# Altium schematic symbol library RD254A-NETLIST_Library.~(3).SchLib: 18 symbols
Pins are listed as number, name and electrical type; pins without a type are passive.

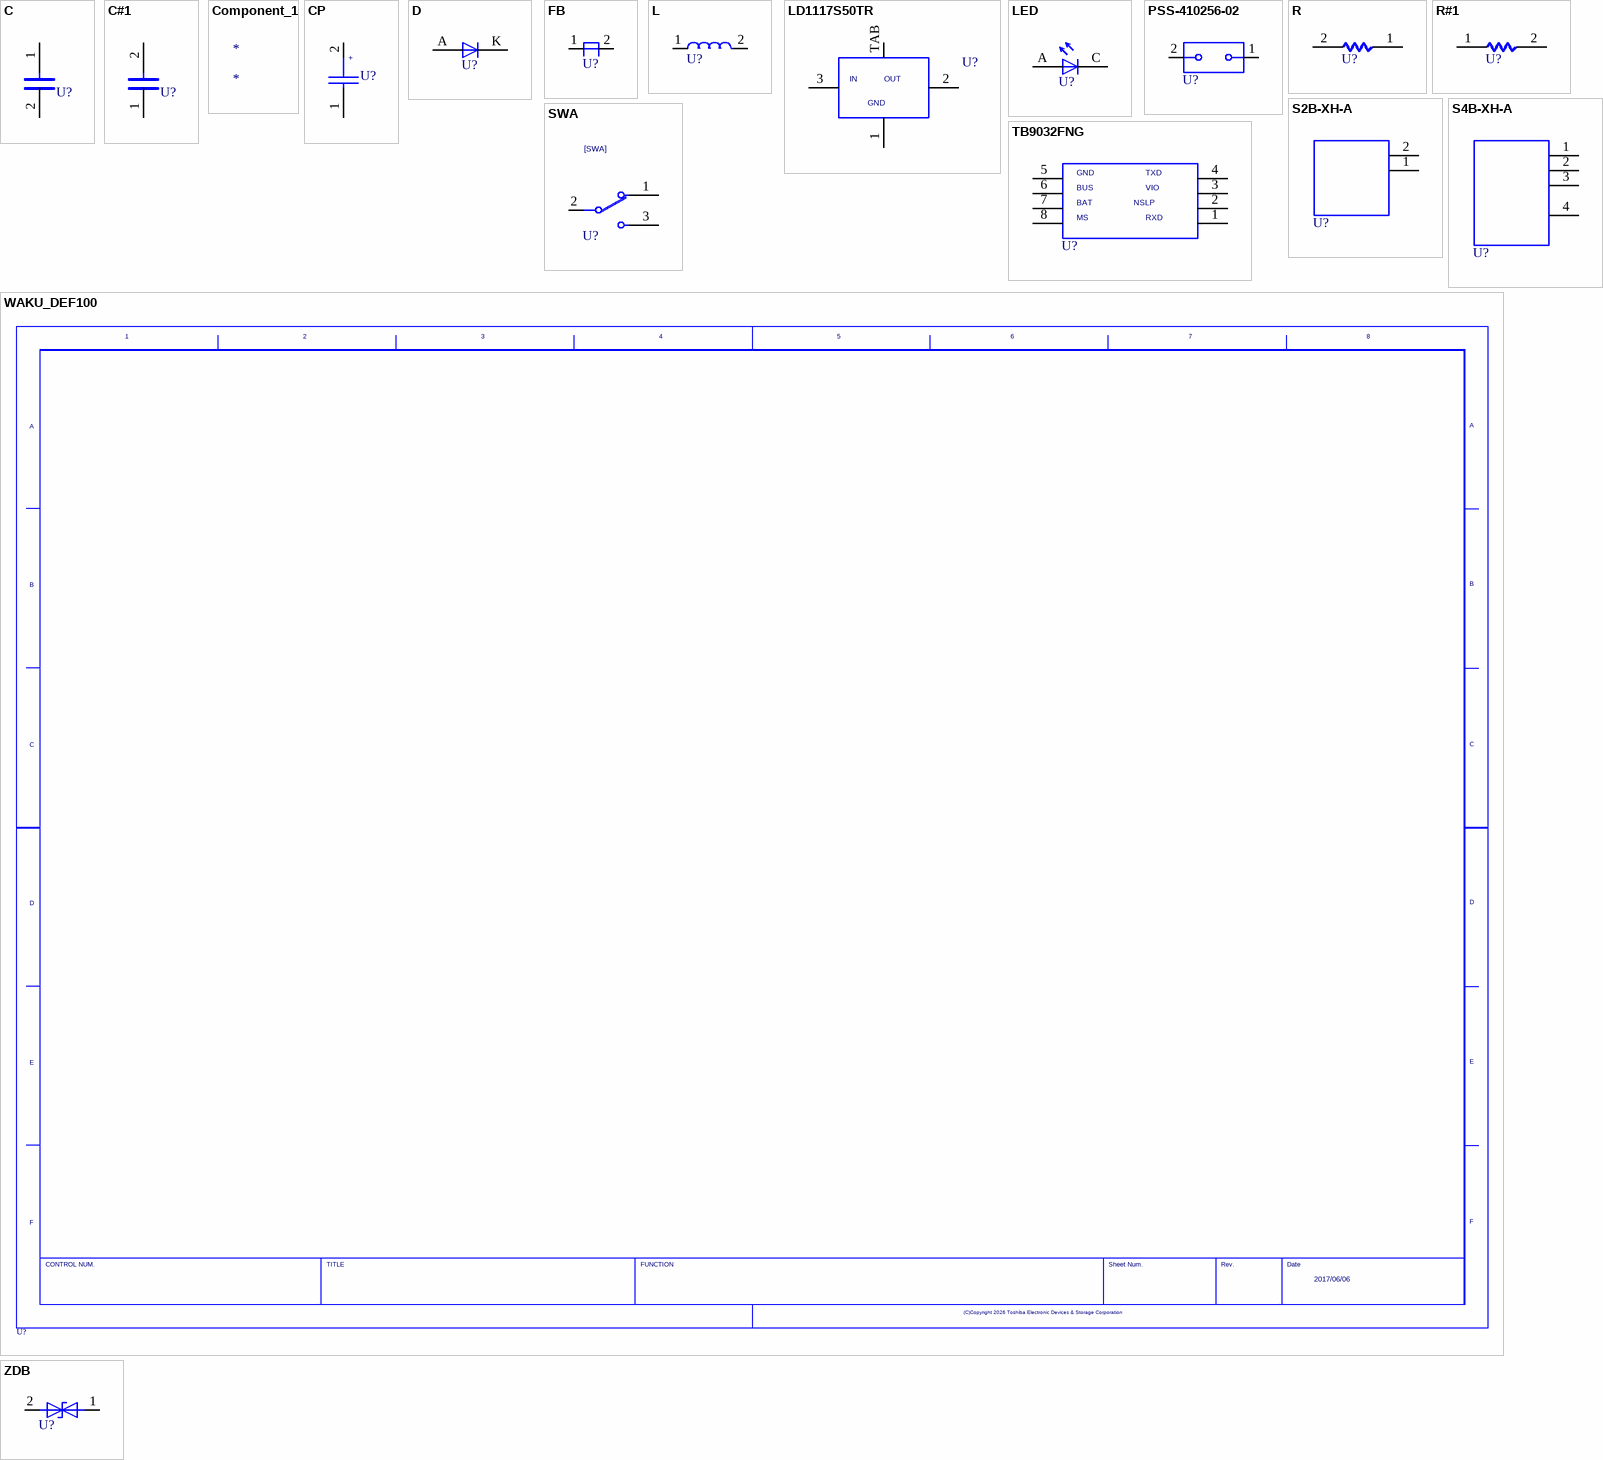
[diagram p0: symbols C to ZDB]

## C
designator U?  (value not drawn)
OriginalSymbolOrigin: (2540,7620); Altium-Right: 20; Altium-Bottom: 10
pins: 1 2, 2 1

## C#1
designator U?, comment C  (value not drawn)
OriginalSymbolOrigin: (2540,7620); Altium-Right: 20; Altium-Bottom: 10
pins: 1, 2

## Component_1
designator *

## CP
designator U?  (value not drawn)
SAVEAREA0: -1450,-153,20294,13055; SAVECOUNT: 52; TIME: 15:02:55; UPDATEUSER: fukuda-y; UPDATETIME: 16:13:42; OriginalSymbolOrigin: (2540,10160); Altium-Right: 20
pins: 1, 2

## D
designator U?  (value not drawn)
SAVEAREA0: -225,-91,12804,7836; SAVECOUNT: 3; TIME: 14:49:55; UPDATEUSER: 19870035; UPDATETIME: 14:20:16; OriginalSymbolOrigin: (5080,5080); Altium-Right: 10; Altium-Bottom: 20
pins: A, K C

## FB
designator U?  (value not drawn)
SAVEAREA0: -63393,-16950,474261,314592; TIME: 14:30:25; UPDATEUSER: t5459927; UPDATETIME: 11:02:03; SAVECOUNT: 20; OriginalSymbolOrigin: (7620,7620); Altium-Right: 10
pins: 1, 2

## L
designator U?  (value not drawn)
OriginalSymbolOrigin: (2540,5080); Altium-Right: 30; Altium-Bottom: 20
pins: 1, 2

## LD1117S50TR
designator U?  (value not drawn)
SAVEAREA0: -63393,-16950,474261,314592; TIME: 14:30:25; UPDATEUSER: t5459927; UPDATETIME: 09:55:03; SAVECOUNT: 16; OriginalSymbolOrigin: (5080,15240); Altium-Right: 60; Altium-Bottom: 40
pins: 1, 2, 3, TAB

## LED
designator U?  (value not drawn)
SAVEAREA0: -6799,-183,19247,15664; TIME: 14:49:55; UPDATEUSER: fukuda-y; UPDATETIME: 13:54:07; SAVECOUNT: 4; OriginalSymbolOrigin: (5080,7620); Altium-Right: 10; Altium-Bottom: 30
pins: A, C

## PSS-410256-02
designator U?  (value not drawn)
SAVEAREA0: -63393,-16950,474261,314592; TIME: 14:30:25; UPDATEUSER: t5459927; UPDATETIME: 18:56:33; SAVECOUNT: 22; OriginalSymbolOrigin: (2540,5080); Altium-Right: 40; Altium-Bottom: 20
pins: 1 2, 2 1

## R
designator U?  (value not drawn)
OriginalSymbolOrigin: (5080,5080); Altium-Right: 20
pins: 1 2, 2 1

## R#1
designator U?, comment R  (value not drawn)
OriginalSymbolOrigin: (5080,5080); Altium-Right: 20
pins: 1, 2

## S2B-XH-A
designator U?  (value not drawn)
SAVEAREA0: -63393,-16950,474261,314592; TIME: 14:30:25; UPDATEUSER: t5459927; UPDATETIME: 11:18:03; SAVECOUNT: 20; OriginalSymbolOrigin: (0,12700); Altium-Right: 50
pins: 1, 2

## S4B-XH-A
designator U?  (value not drawn)
SAVEAREA0: -63393,-16950,474261,314592; TIME: 14:30:25; UPDATEUSER: t5459927; UPDATETIME: 17:06:20; SAVECOUNT: 19; OriginalSymbolOrigin: (0,12700); Altium-Right: 50; Altium-Bottom: 70
pins: 1, 2, 3, 4

## SWA
designator U?  (value not drawn)
OriginalSymbolOrigin: (2540,10160); Altium-Right: 30; Altium-Bottom: 40
pins: 1, 2, 3

## TB9032FNG
designator U?  (value not drawn)
SAVEAREA0: -63393,-16950,474261,314592; TIME: 14:30:25; UPDATEUSER: t5459927; UPDATETIME: 14:36:30; SAVECOUNT: 16; OriginalSymbolOrigin: (5080,12700); Altium-Right: 90; Altium-Bottom: 50
pins: 1, 2, 3, 4, 5, 6, 7, 8

## WAKU_DEF100
designator U?  DATE: 2017/06/06  (hidden comment: WAKU_DEF100)
PLOTTIME: HH:MM; SAVEAREA0: -63393,-16950,474261,314592; TIME: 14:30:25; UPDATEUSER: t5459927; UPDATETIME: 10:44:05; SAVECOUNT: 5; OriginalSymbolOrigin: (10160,284480); Altium-Right: 1570; Altium-Bottom: 1070

## ZDB
designator U?  (value not drawn)
SAVEAREA0: -4630,-153,17114,13055; TIME: 14:49:55; UPDATEUSER: fukuda-y; UPDATETIME: 08:22:19; SAVECOUNT: 6; OriginalSymbolOrigin: (2540,5080); Altium-Right: 30; Altium-Bottom: 20
pins: 1 2, 2 1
